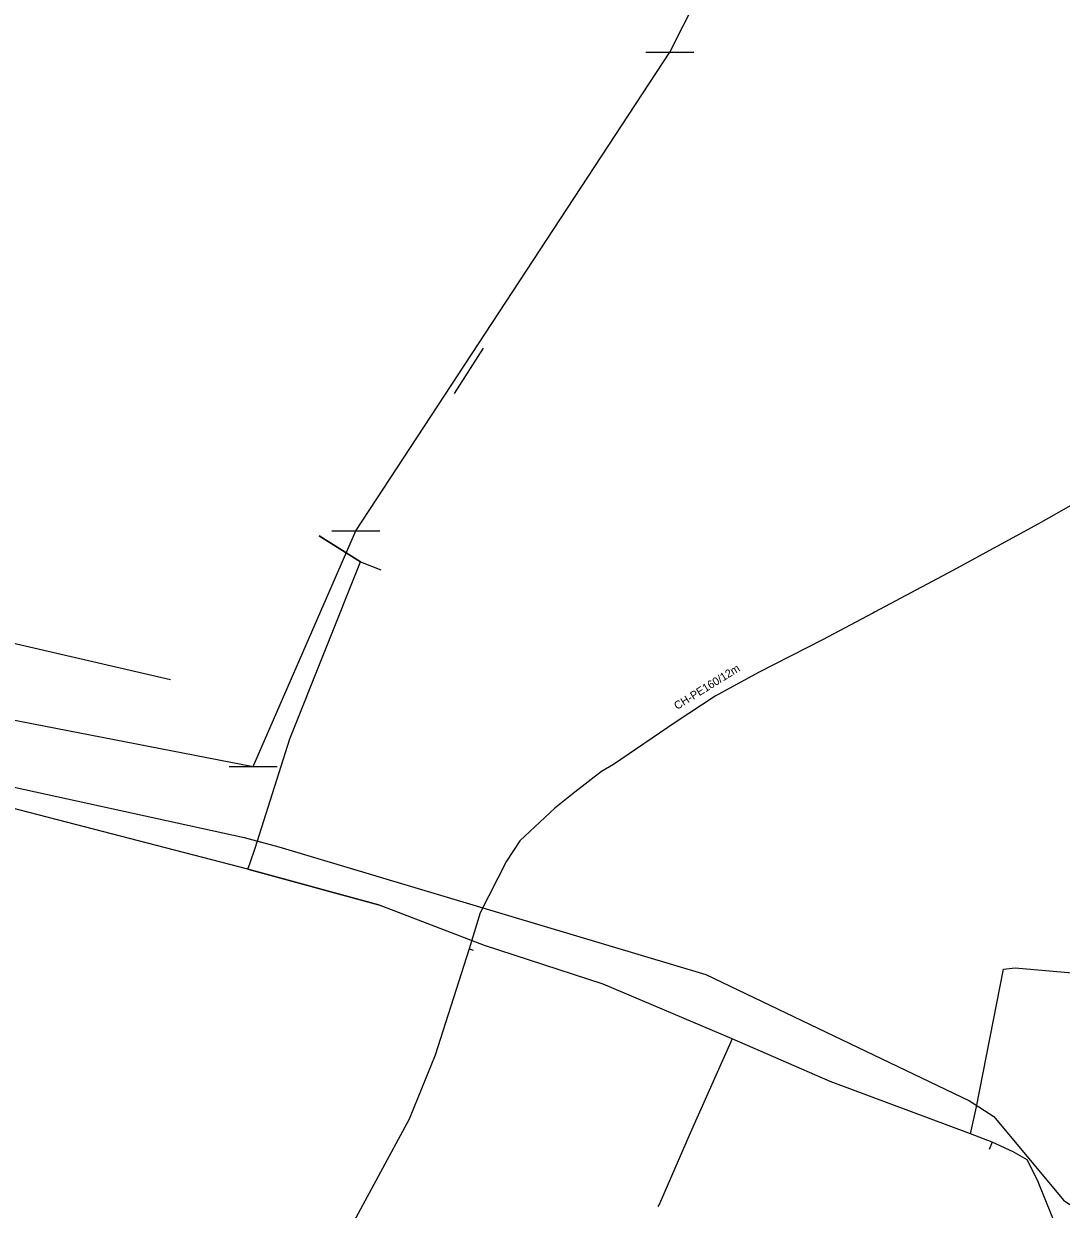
# Model space of a CAD drawing. Extents: x -543464 to -538545, y -1098769 to -1093672.
# Drawn here: x -541432.9 to -541368.1, y -1096848.4 to -1096774.4 of the extents above; entities that cross this region are included whole.
import ezdxf

# ---------------------------------------------------------------- set-up
doc = ezdxf.new("R2010")
doc.units = 0
for name, color, linetype in [('07_ELEKTRO', 7, 'Continuous'), ('07_KANALIZACE', 7, 'Continuous'), ('07_SDĚLOVACÍ', 7, 'Continuous'), ('07_VODOVOD', 7, 'Continuous'), ('Default', 7, 'Continuous')]:
    doc.layers.add(name, color=color, linetype=linetype)

# ---------------------------------------------------------------- blocks, each defined once
blk = doc.blocks.new('S_1')
at = {"layer": 'Default'}
blk.add_lwpolyline([(-0.0381, 0), (0.0381, 0)], dxfattribs=at)

msp = doc.modelspace()

# ---------------------------------------------------------------- linework, layer by layer
at = {"layer": '07_ELEKTRO'}
msp.add_lwpolyline([(-541423.75, -1096815.38), (-541453.24, -1096808.55)], dxfattribs=at)
at = {"layer": '07_KANALIZACE'}
for p, q in [((-541392.578, -1096776.203), (-541382.645, -1096756.442)), ((-541412.175, -1096806.092), (-541392.578, -1096776.203)), ((-541404.234, -1096794.682), (-541406.034, -1096797.515)), ((-541418.598, -1096820.803), (-541412.175, -1096806.092)), ((-541459.762, -1096812.806), (-541418.598, -1096820.803))]:
    msp.add_line(p, q, dxfattribs=at)
at = {"layer": '07_SDĚLOVACÍ'}
for points in [[(-541477.94, -1096783.28), (-541470.59, -1096787.92), (-541462.98, -1096786.3), (-541459.65, -1096787.37), (-541456.79, -1096787.88), (-541452.07, -1096794.89), (-541449.55, -1096806.45), (-541449.9, -1096811.01), (-541450.8, -1096820.68), (-541449.73, -1096822.65), (-541447.17, -1096821.86), (-541444.55, -1096819.68), (-541419.16, -1096825.24), (-541416.98, -1096825.81), (-541390.32, -1096833.78), (-541373.87, -1096841.67), (-541372.36, -1096842.66), (-541368.01, -1096847.88), (-541364.56, -1096850.18), (-541359.31, -1096852.4), (-541356.54, -1096853.33)], [(-541414.46, -1096806.4), (-541411.89, -1096808.01)], [(-541411.89, -1096808.01), (-541414.46, -1096806.4)], [(-541373.81, -1096843.73), (-541373.44, -1096842.05), (-541371.74, -1096833.45), (-541371.02, -1096833.38), (-541363.9, -1096834), (-541360.23, -1096833.4), (-541359.44, -1096833.21), (-541352.66, -1096821.86), (-541352.86, -1096820.02), (-541345.75, -1096807.66)], [(-541418.77, -1096826.81), (-541418.46, -1096825.89), (-541416.3, -1096819.07), (-541411.89, -1096808.01)], [(-541411.89, -1096808.01), (-541410.62, -1096808.52)], [(-541418.46, -1096825.89), (-541416.3, -1096819.07)], [(-541418.92, -1096827.2), (-541443.35, -1096820.88), (-541445.47, -1096820.56), (-541461.47, -1096821.14), (-541473.15, -1096823.13)], [(-541418.92, -1096827.2), (-541418.77, -1096826.81)], [(-541418.92, -1096827.2), (-541410.77, -1096829.44)], [(-541388.68, -1096837.81), (-541396.73, -1096834.39), (-541404.14, -1096831.98), (-541410.77, -1096829.44), (-541418.92, -1096827.2)], [(-541373.44, -1096842.05), (-541371.74, -1096833.45)], [(-541388.68, -1096837.81), (-541391.31, -1096843.69), (-541393.23, -1096848.1), (-541393.33, -1096848.28)], [(-541373.81, -1096843.73), (-541382.56, -1096840.46), (-541388.68, -1096837.81)], [(-541373.87, -1096841.67), (-541372.36, -1096842.66)], [(-541372.45, -1096844.26), (-541373.81, -1096843.73)], [(-541380.24, -1096872.73), (-541378.03, -1096868.5), (-541375.79, -1096864.44), (-541368.27, -1096849.99), (-541369.63, -1096846.62), (-541370.28, -1096845.36), (-541371.15, -1096844.85), (-541372.45, -1096844.26)], [(-541372.45, -1096844.26), (-541372.65, -1096844.72)]]:
    msp.add_lwpolyline(points, dxfattribs=at)
at = {"layer": '07_VODOVOD'}
for p, q in [((-541405.11, -1096832.188), (-541405.04, -1096832.203)), ((-541405.04, -1096832.203), (-541404.855, -1096832.263))]:
    msp.add_line(p, q, dxfattribs=at)
for points in [[(-541366.911, -1096804.149), (-541369.56, -1096805.653), (-541374.908, -1096808.567), (-541379.794, -1096811.163), (-541379.903, -1096811.22), (-541383.055, -1096812.895), (-541387.033, -1096814.926), (-541389.757, -1096816.405), (-541392.241, -1096818.06), (-541396.099, -1096820.673), (-541396.854, -1096821.118), (-541398.513, -1096822.403), (-541399.762, -1096823.392), (-541401.937, -1096825.446), (-541402.776, -1096826.711), (-541404.41, -1096829.934), (-541405.11, -1096832.188)], [(-541405.11, -1096832.188), (-541407.224, -1096838.82), (-541408.848, -1096842.814), (-541412.727, -1096849.986), (-541416.2, -1096856.433), (-541418.955, -1096862.809), (-541421.258, -1096867.103), (-541421.883, -1096868.197), (-541422.153, -1096868.547), (-541424.397, -1096872.006), (-541425.151, -1096873.43)]]:
    msp.add_lwpolyline(points, dxfattribs=at)

# ---------------------------------------------------------------- block references
at = {"layer": '07_KANALIZACE', "xscale": 39.3602801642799, "yscale": 39.36028016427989, "rotation": -0.010678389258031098}
for p in [(-541392.578, -1096776.203), (-541412.175, -1096806.092), (-541418.598, -1096820.803)]:
    msp.add_blockref('S_1', p, dxfattribs=at)

# ---------------------------------------------------------------- texts
at = {"layer": '07_VODOVOD'}
msp.add_text('CH-PE160/12m', height=0.49983, rotation=31.88361, dxfattribs=at).set_placement((-541392.123, -1096817.275))

doc.saveas('drawing.dxf')
